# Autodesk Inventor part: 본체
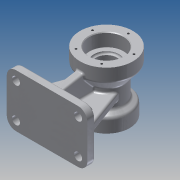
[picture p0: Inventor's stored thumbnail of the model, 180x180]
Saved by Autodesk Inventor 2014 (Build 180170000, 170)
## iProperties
Created: 2015-08
Part Number: 본체
Material: 알루미늄 6061
Document SubType Name: Modeling
Designer: SDA21
Density: 2.71 g/cm^3
Appearance: 알루미늄 - 평지
Author: SDA21
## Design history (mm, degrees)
sketch "스케치1"
  geometry: 1 further point
sketch "스케치2"
  geometry: C1 r 35 at (0, 0); 1 further point
  constraints: 1 centre point, 1 coincident
  dimensions: "d0" = 70 diameter of C1
extrude "돌출1" new body sketch "스케치2" distance "d1" = 20; taper "d2" = 0 deg
sketch "스케치3"
  geometry: C1 r 35 at (0, 0) reference; C2 r 26 at (0, 0)
  constraints: 1 centre point, 1 coincident
  dimensions: "d3" = 52 diameter of C2
extrude "돌출2" join sketch "스케치3" distance "d4" = 50; taper "d5" = 0 deg
sketch "스케치4"
  geometry: C1 r 26 at (0, 0) reference; C2 r 40 at (0, 0)
  constraints: 1 centre point, 1 coincident
  dimensions: "d6" = 80 diameter of C2
extrude "돌출3" join sketch "스케치4" distance "d7" = 20; taper "d8" = 0 deg
sketch "스케치5"
  geometry: L1 (35, 20)-(35, 0) reference; L2 (35, 0)-(-35, 0) reference; L3 (-35, 0)-(-35, 20) reference; L4 (-35, 20)-(-26, 20) reference; L5 (-26, 20)-(-26, 70) reference; L6 (-26, 70)-(-40, 70) reference; L7 (-40, 70)-(-40, 90) reference; L8 (-40, 90)-(40, 90) reference; L9 (40, 90)-(40, 70) reference; L10 (40, 70)-(26, 70) reference; L11 (26, 70)-(26, 20) reference; L12 (26, 20)-(35, 20) reference; L13 (35, 20)-(26, 25.196); L14 (35, 20)-(45.392, 20); L15 (26, 25.196)-(26, 20); L16 (35, 20)-(26, 20); L17 (40, 70)-(26, 53.315); L18 (40, 70)-(61.78, 70); L19 (26, 53.315)-(26, 70); L20 (40, 70)-(26, 70); L21 (0, -18)-(0, 108) reference; 1 further point
  constraints: 16 end point, 2 collinear, 2 equal length, 2 horizontal, 2 perpendicular, 2 point on line
  dimensions: "d9" = 150 deg angle of L14 L13; "d10" = 130 deg angle of L17 L18
revolve "회전1" sketch "스케치5" stored, may be unused: angle "d11" = 90 deg
node "작업 평면1"
sketch "스케치6"
  geometry: L1 (47, 0)-(-47, 0); L2 (-61, 14)-(-61, 66); L3 (-47, 80)-(47, 80); L4 (61, 66)-(61, 14); A1 r 14 centre (47, 66) between (61, 66) and (47, 80); A2 r 14 centre (47, 14) between (47, 0) and (61, 14); A3 r 14 centre (-47, 14) between (-61, 14) and (-47, 0); A4 r 14 centre (-47, 66) between (-47, 80) and (-61, 66); 4 further points
  constraints: 8 end point, 8 point on circle, 8 tangent, 6 point on line, 4 centre point, 3 equal radius, 2 parallel, 1 horizontal, 1 perpendicular
  dimensions: "d14" = 122 distance of point (-61, 80) point (61, 80); "d15" = 80 distance of point (-61, 0) point (-61, 80); "d16" = 14 radius of A1
extrude "돌출4" join sketch "스케치6" distance "d17" = 12; taper "d18" = 0 deg
sketch "스케치7"
  geometry: L1 (-61, -66)-(-61, -14) reference; L2 (-47, 0)-(47, 0) reference; L3 (61, -14)-(61, -66) reference; L4 (47, -80)-(-47, -80) reference; L5 (-51, -34)-(-51, -46); L6 (51, -46)-(51, -34); L7 (6, -10)-(-6, -10); L8 (-6, -70)-(6, -70); L9 (-6, -10)-(-6, -34); L10 (-6, -46)-(-6, -70); L11 (6, -70)-(6, -46); L12 (6, -34)-(6, -10); L13 (51, -34)-(6, -34); L14 (-6, -34)-(-51, -34); L15 (-51, -46)-(-6, -46); L16 (6, -46)-(51, -46); A1 r 14 centre (-47, -66) between (-61, -66) and (-47, -80) reference; A2 r 14 centre (-47, -14) between (-47, 0) and (-61, -14) reference; A3 r 14 centre (47, -14) between (61, -14) and (47, 0) reference; A4 r 14 centre (47, -66) between (47, -80) and (61, -66) reference; 1 further point
  constraints: 24 end point, 10 parallel, 4 perpendicular, 3 horizontal
  dimensions: "d23" = 102 distance of L6.start L5.end; "d24" = 12 distance of L5.end L5.start; "d25" = 12 distance of L8.end L8.start; "d26" = 60 distance of L8.start L7.end
extrude "돌출5" join sketch "스케치7" distance "d27" = 78; taper "d28" = 0 deg
sketch "스케치8"
  geometry: L1 (0, 52.702)-(7.315, 52.702) reference; L2 (0, 0)-(0, 52.702) reference; L3 (24, 0)-(0, 0) reference; L4 (24, 0)-(24, 38.453) reference; 5 further points
  constraints: 3 other
sketch "스케치9"
  geometry: L1 (44, 117.547)-(44, 38.453) reference; L2 (24, 38.453)-(24, 0) reference; L3 (0, 0)-(24, 0) reference; L4 (0, 52.702)-(0, 0) reference; L5 (7.315, 52.702)-(0, 52.702) reference; L6 (-46, 112.482)-(-26, 112.482) reference; L7 (-46, 43.518)-(-46, 112.482) reference; L8 (-36, 43.518)-(-46, 43.518) reference; L9 (-36, 0)-(-36, 43.518) reference; L10 (-36, 0)-(-12, 0) reference; L11 (-12, 0)-(-12, 52.702) reference; L12 (-12, 52.702)-(-20.804, 52.702) reference; L13 (-26, 43.518)-(-36, 43.518) reference; L14 (24, 0)-(34, 0) reference; L15 (34, 0)-(34, -12) reference; L16 (34, -12)-(-46, -12) reference; L17 (-46, -12)-(-46, 0) reference; L18 (-46, 0)-(-36, 0) reference; L19 (24, 0)-(31.053, 40); L20 (24, 0)-(64.617, 0); L21 (31.053, 40)-(24, 40); L22 (24, 40)-(24, 0); L23 (44, 38.453)-(24, 38.453) reference; L24 (24, 117.547)-(44, 117.547) reference; L25 (-20.804, 103.298)-(7.315, 103.298) reference; 1 further point
  constraints: 8 end point, 1 collinear, 1 equal length, 1 horizontal, 1 parallel, 4 other
  dimensions: "d29" = 80 deg angle of L20 L19
extrude "돌출6" join sketch "스케치9" distance "d30" = 12; taper "d31" = 0 deg
sketch "스케치10"
  geometry: L1 (0, 0)-(0, 78) reference; L2 (112, 0)-(112, -12) reference; L3 (112, -12)-(-10, -12) reference; L4 (-10, -12)-(-10, 0) reference; L5 (-10, 0)-(0, 0) reference; L6 (0, 0)-(0, 78) reference; L7 (0, 78)-(25, 78) reference; L8 (45, 0)-(45, 52.702) reference; L9 (0, 0)-(45, 0) reference; L10 (102, 0)-(112, 0) reference; L11 (102, 78)-(102, 0) reference; L12 (77, 78)-(102, 78) reference; L13 (57, 52.702)-(57, 0) reference; L14 (57, 0)-(102, 0) reference; L15 (0, 0)-(25.909, 71.185); L16 (0, 0)-(75.753, 0); L17 (25, 78)-(0, 78); L18 (0, 0)-(0, 78); L19 (51, 0)-(51, 78); L20 (102, 0)-(76.091, 71.185); L21 (102, 0)-(102, 78); L22 (102, 78)-(77, 78); A1 r 26 centre (51, 78) between (25, 78) and (45, 52.702) reference; A2 r 26 centre (51, 78) between (25, 78) and (45, 52.702) reference; A3 r 26 centre (51, 78) between (57, 52.702) and (77, 78) reference; A4 r 26 centre (51, 78) between (77, 78) and (25, 78) reference; A5 r 26 centre (51, 78) between (25, 78) and (25.909, 71.185); A6 r 26 centre (51, 78) between (76.091, 71.185) and (77, 78)
  constraints: 18 end point, 5 point on circle, 2 centre point, 2 parallel, 1 coincident, 1 collinear, 1 equal length, 1 horizontal, 1 point on line, 1 symmetric about line, 1 other
  dimensions: "d32" = 70 deg angle of L16 L15
extrude "돌출7" cut sketch "스케치10" distance "d33" = 12; taper "d34" = 0 deg
fillet "모깎기2" dims "d35" = 3
sketch "스케치11"
  geometry: C1 r 6 at (47, 14); A1 r 14 centre (47, 14) between (47, 0) and (61, 14) reference; 1 further point
  constraints: 1 centre point, 1 coincident
  dimensions: "d37" = 12 diameter of C1
extrude "돌출8" cut sketch "스케치11" distance "d38" = 12; taper "d39" = 0 deg
node "작업 평면2"
sketch "스케치12"
  geometry: L1 (107.716, -3)-(107.716, -15) reference; L2 (107.716, -15)-(-14.284, -15) reference; L3 (-14.284, -15)-(-14.284, -3) reference; L4 (16.716, 21)-(16.716, 15); L5 (28.716, 15)-(28.716, 21); L6 (37.716, 50.607)-(37.716, -3) reference; L7 (-1.092, -3)-(37.716, -3) reference; L8 (-14.284, -3)-(-1.092, -3) reference; L9 (94.523, -3)-(107.716, -3) reference; L10 (55.716, -3)-(94.523, -3) reference; L11 (55.716, 50.607)-(55.716, -3) reference; L12 (23.234, 63.836)-(-1.092, -3) reference; L13 (94.523, -3)-(70.197, 63.836) reference; A1 r 6 centre (22.716, 15) between (16.716, 15) and (28.716, 15); A2 r 6 centre (22.716, 21) between (28.716, 21) and (16.716, 21); A3 r 26 centre (46.716, 75) between (55.716, 50.607) and (70.197, 63.836) reference; A4 r 26 centre (46.716, 75) between (70.197, 63.836) and (23.234, 63.836) reference; A5 r 26 centre (46.716, 75) between (23.234, 63.836) and (37.716, 50.607) reference
  constraints: 4 end point, 4 point on circle, 2 centre point, 2 tangent
extrude "돌출9" cut sketch "스케치12" distance "d49" = 12; taper "d50" = 0 deg
sketch "스케치13"
  geometry: C1 r 40 at (0, 0) reference; C2 r 26 at (0, 0)
  constraints: 1 centre point, 1 coincident
  dimensions: "d51" = 52 diameter of C2
extrude "돌출10" cut sketch "스케치13" distance "d52" = 20; taper "d53" = 0 deg
sketch "스케치14"
  geometry: C1 r 35 at (0, 0) reference; C2 r 20 at (0, 0)
  constraints: 1 centre point, 1 coincident
  dimensions: "d54" = 40 diameter of C2
extrude "돌출11" cut sketch "스케치14" distance "d55" = 17; taper "d56" = 0 deg
sketch "스케치15"
  geometry: C1 r 26 at (0, 0) reference; C2 r 19 at (0, 0)
  constraints: 1 centre point, 1 coincident
  dimensions: "d57" = 38 diameter of C2
extrude "돌출12" cut sketch "스케치15" distance "d58" = 3; taper "d59" = 0 deg
sketch "스케치16"
  geometry: C1 r 19 at (0, 0) reference; C2 r 16 at (0, 0)
  constraints: 1 centre point, 1 coincident
  dimensions: "d60" = 32 diameter of C2
extrude "돌출13" cut sketch "스케치16" stored distance "d61" = 3; taper "d62" = 0 deg
chamfer "모따기1" distance "d63" = 1; stored, may be unused: second distance "d64" = 2, angle "d65" = 45 deg
fillet "모깎기4" dims "d66" = 3
fillet "모깎기5" dims "d67" = 0.3
fillet "모깎기6" dims "d68" = 5
fillet "모깎기7" dims "d69" = 3
sketch "스케치17" dims "d70" = 66
  geometry: C1 r 27 at (0, 0) reference; C2 r 2 at (0, 33); 1 further point
  constraints: 1 centre point, 1 coincident, 1 vertical alignment, 2 other
  dimensions: "d71" = 4 diameter of C2
hole "구멍1" sketch "스케치17" at (0, 33) diameter "d72" = 3.242; stored, may be unused: countersink angle "d76" = 90 deg, drill point angle "d78" = 118 deg; dims "d73" = 10, "d74" = 4, "d75" = 2, "d77" = 13
sketch "스케치18" dims "d82" = 54
  geometry: C1 r 21 at (0, 0) reference; C2 r 2 at (0, 27); 1 further point
  constraints: 1 centre point, 1 coincident, 1 vertical alignment, 2 other
  dimensions: "d83" = 4 diameter of C2
hole "구멍2" sketch "스케치18" at (0, 27) diameter "d84" = 3.242; stored, may be unused: countersink angle "d88" = 90 deg, drill point angle "d90" = 118 deg; dims "d85" = 10, "d86" = 4, "d87" = 2, "d89" = 13
sketch "스케치19"
  geometry: L1 (39, 99.99)-(39, 93.028) reference; L2 (36, 89.832)-(-14, 89.832) reference; L3 (-14, 89.832)-(-14, 93.764) reference; L4 (-14.3, 94.079)-(-30, 94.079) reference; L5 (-31, 95.125)-(-31, 109.482) reference; L6 (-31, 109.482)-(-13.887, 109.482) reference; L7 (-2.917, 100.298)-(20.496, 100.298) reference; L8 (40.82, 114.547)-(59, 114.547) reference; L9 (59, 114.547)-(59, 101.325) reference; L10 (58, 100.298)-(39.3, 100.298) reference; L11 (39.3, 49.702)-(58, 49.702) reference; L12 (59, 48.675)-(59, 35.453) reference; L13 (59, 35.453)-(47.196, 35.453) reference; L14 (42.293, 32.952)-(40.82, 32.952) reference; L15 (20.496, 47.432)-(18, 47.432) reference; L16 (18, 47.432)-(18, 0) reference; L17 (18, 0)-(36.483, 0) reference; L18 (36.483, 0)-(42.293, 32.952) reference; L19 (39, 56.972)-(39, 50.01) reference; L20 (-14, 60.168)-(36, 60.168) reference; L21 (-14, 56.236)-(-14, 60.168) reference; L22 (-30, 55.921)-(-14.3, 55.921) reference; L23 (-31, 40.518)-(-31, 54.875) reference; L24 (-22.863, 40.518)-(-31, 40.518) reference; L25 (-18, 0)-(-18, 38.081) reference; L26 (-28, -3)-(-23.196, -3) reference; L27 (-31, -15)-(-31, -6) reference; L28 (49, -15)-(-31, -15) reference; L29 (49, -6)-(49, -15) reference; L30 (41.759, -3)-(46, -3) reference; L31 (-13.887, 38.081)-(-18, 38.081) reference; L32 (0, 47.432)-(-2.917, 47.432) reference; L33 (0, 47.432)-(0, 0) reference; L34 (-18, 0)-(0, 0) reference; L35 (-31, -15)-(-31, 21); L36 (-31, 21)-(-5, 21); A1 r 3 centre (-28, -6) between (-28, -3) and (-31, -6) reference; A2 r 3 centre (46, -6) between (49, -6) and (46, -3) reference; 10 further points
  constraints: 4 end point, 2 perpendicular, 1 coincident, 27 other
  dimensions: "d96" = 36 distance of L27.start L35.end; "d97" = 26 distance of L35.end L36.end
feature "엠보싱1" sketch "스케치19" dims "d0" = 70, "d98" = 0.5, "d99" = 0
node "솔리드1"
pattern_linear "직사각형 패턴1" dims "d42" = 94, "d45" = 52
pattern_circular "원형 패턴1" dims angle "d80" = 360 deg
pattern_circular "원형 패턴2" dims angle "d92" = 360 deg
mirror "대칭2"
node "절단 모서리 투영1"
node "절단 모서리 투영2"
node "절단 모서리 투영3"
node "절단 모서리 투영4"
node "절단 모서리 투영5"
node "절단 모서리 투영6"
